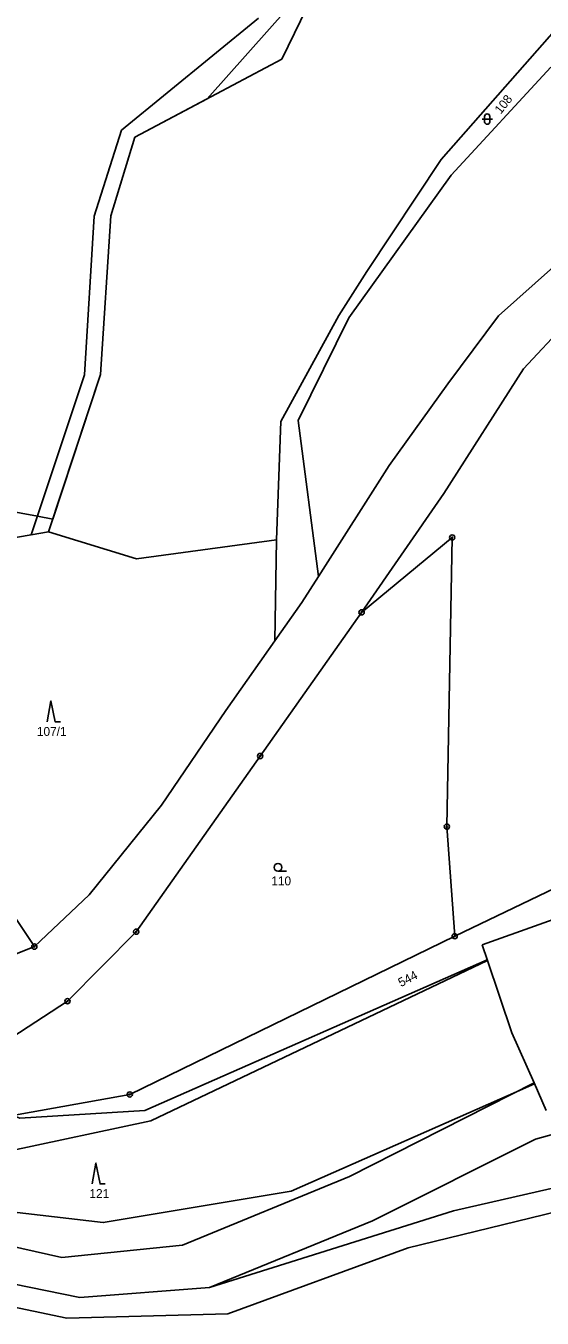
# Model space of a CAD drawing. Extents: x -547623 to -538651, y -1096714 to -1086522.
# Drawn here: x -544480.8 to -544381.9, y -1094558.3 to -1094310.7 of the extents above; entities that cross this region are included whole.
import ezdxf

# ---------------------------------------------------------------- set-up
doc = ezdxf.new("R2010")
doc.units = 0
for name, color, linetype in [('Vrstva 1', 7, 'Continuous'), ('Vrstva 25', 7, 'Continuous'), ('Vrstva 52', 7, 'Continuous'), ('Vrstva 83', 7, 'Continuous'), ('Vrstva 86', 7, 'Continuous')]:
    doc.layers.add(name, color=color, linetype=linetype)

msp = doc.modelspace()

# ---------------------------------------------------------------- linework, layer by layer
at = {"layer": 'Vrstva 1'}
for points in [[(-544419.77, -1094292.39), (-544431.79, -1094317.13)], [(-544401.22, -1094336.37), (-544365.84, -1094296.09)], [(-544462.49, -1094330.71), (-544436.24, -1094309.29)], [(-544431.79, -1094317.13), (-544459.96, -1094332.09)], [(-544380.24, -1094318.64), (-544399.29, -1094339.34)], [(-544467.74, -1094347.2), (-544462.49, -1094330.71)], [(-544459.96, -1094332.09), (-544464.57, -1094347.15)], [(-544415.46, -1094357.78), (-544401.22, -1094336.37)], [(-544399.29, -1094339.34), (-544418.93, -1094366.66)], [(-544469.56, -1094377.62), (-544467.74, -1094347.2)], [(-544464.57, -1094347.15), (-544466.54, -1094377.51)], [(-544420.85, -1094366.26), (-544415.46, -1094357.78)], [(-544390.22, -1094366.32), (-544379.71, -1094356.93)], [(-544431.95, -1094386.55), (-544420.85, -1094366.26)], [(-544418.93, -1094366.66), (-544428.64, -1094386.32)], [(-544399.96, -1094379.3), (-544390.22, -1094366.32)], [(-544385.44, -1094376.43), (-544377.33, -1094367.74)], [(-544469.56, -1094377.62), (-544479.78, -1094408.26)], [(-544476.5, -1094407.7), (-544466.54, -1094377.51)], [(-544400.75, -1094400.36), (-544385.44, -1094376.43)], [(-544411.21, -1094394.96), (-544399.96, -1094379.3)], [(-544432.76, -1094409.19), (-544431.95, -1094386.55)], [(-544428.64, -1094386.32), (-544424.74, -1094416.22)], [(-544424.74, -1094416.22), (-544411.21, -1094394.96)], [(-544416.48, -1094423.1), (-544400.75, -1094400.36)], [(-544479.78, -1094408.26), (-544476.5, -1094407.7)], [(-544476.5, -1094407.7), (-544459.63, -1094412.82)], [(-544485.43, -1094409.22), (-544479.78, -1094408.26)], [(-544459.63, -1094412.82), (-544432.76, -1094409.19)], [(-544432.76, -1094409.19), (-544433.11, -1094428.56)], [(-544416.48, -1094423.1), (-544399.11, -1094408.75)], [(-544399.11, -1094408.75), (-544400.13, -1094464.15)], [(-544427.91, -1094421.19), (-544424.74, -1094416.22)], [(-544433.11, -1094428.56), (-544427.91, -1094421.19)], [(-544435.92, -1094450.63), (-544416.48, -1094423.1)], [(-544442.51, -1094441.89), (-544433.11, -1094428.56)], [(-544454.81, -1094460.05), (-544442.51, -1094441.89)], [(-544459.67, -1094484.27), (-544435.92, -1094450.63)], [(-544479.2, -1094487.13), (-544497.09, -1094460.28)], [(-544468.71, -1094477.24), (-544454.81, -1094460.05)], [(-544400.13, -1094464.15), (-544398.64, -1094485.14)], [(-544393.36, -1094486.79), (-544348.76, -1094470.87)], [(-544398.64, -1094485.14), (-544374.54, -1094473.56)], [(-544479.2, -1094487.13), (-544468.71, -1094477.24)], [(-544472.85, -1094497.6), (-544459.67, -1094484.27)], [(-544494.29, -1094493.18), (-544479.2, -1094487.13)], [(-544398.64, -1094485.14), (-544460.91, -1094515.46)], [(-544393.36, -1094486.79), (-544392.36, -1094489.78)], [(-544456.89, -1094520.54), (-544392.36, -1094489.78)], [(-544392.36, -1094489.78), (-544387.72, -1094503.66)], [(-544483.53, -1094504.55), (-544472.85, -1094497.6)], [(-544387.72, -1094503.66), (-544383.43, -1094513.26)], [(-544418.83, -1094531.18), (-544383.43, -1094513.26)], [(-544383.43, -1094513.26), (-544381.08, -1094518.51)], [(-544460.91, -1094515.46), (-544484.09, -1094519.61)], [(-544383.15, -1094524.05), (-544351.6, -1094515.28)], [(-544484.38, -1094526.41), (-544456.89, -1094520.54)], [(-544383.15, -1094524.05), (-544414.38, -1094539.67)], [(-544418.83, -1094531.18), (-544450.78, -1094544.34)], [(-544362.26, -1094529.36), (-544398.89, -1094537.76)], [(-544407.55, -1094544.87), (-544363.31, -1094534.07)], [(-544473.96, -1094546.71), (-544513.47, -1094537.82)], [(-544398.89, -1094537.76), (-544445.63, -1094552.46)], [(-544414.38, -1094539.67), (-544445.63, -1094552.46)], [(-544470.45, -1094554.36), (-544531.27, -1094541.95)], [(-544450.78, -1094544.34), (-544473.96, -1094546.71)], [(-544442.13, -1094557.51), (-544407.55, -1094544.87)], [(-544510.16, -1094550.54), (-544472.99, -1094558.31)], [(-544445.63, -1094552.46), (-544470.45, -1094554.36)], [(-544472.99, -1094558.31), (-544442.13, -1094557.51)]]:
    msp.add_lwpolyline(points, dxfattribs=at)
at = {"layer": 'Vrstva 25'}
for p, q in [((-544393.4, -1094328.6), (-544391.4, -1094328.6)), ((-544392.9, -1094329.1), (-544392.9, -1094328.1)), ((-544391.9, -1094328.1), (-544391.9, -1094329.1)), ((-544432.5, -1094472.7), (-544430.9, -1094472.7))]:
    msp.add_line(p, q, dxfattribs=at)
for points in [[(-544476.71, -1094444.06), (-544476.01, -1094440.06), (-544475.21, -1094444.06), (-544474.21, -1094444.06)], [(-544468.11, -1094532.59), (-544467.41, -1094528.59), (-544466.61, -1094532.59), (-544465.61, -1094532.59)]]:
    msp.add_lwpolyline(points, dxfattribs=at)
msp.add_circle((-544432.5, -1094471.95), 0.75, dxfattribs=at)
for centre, start, end in [((-544392.4, -1094328.1), 0, 180), ((-544392.4, -1094329.1), 180, 0)]:
    msp.add_arc(centre, 0.5, start, end, dxfattribs=at)
at = {"layer": 'Vrstva 52'}
for points in [[(-544422.69, -1094298.4), (-544446.09, -1094324.72), (-544459.96, -1094332.09), (-544464.57, -1094347.15), (-544466.54, -1094377.51), (-544475.68, -1094405.23), (-544478.59, -1094404.69), (-544490.5, -1094402.5)], [(-544386.24, -1094514.68), (-544430, -1094534), (-544466, -1094540), (-544487.5, -1094537.5), (-544536.5, -1094523.5), (-544567.5, -1094506), (-544566.1, -1094505.65), (-544561.5, -1094504.5), (-544534.5, -1094509), (-544505.75, -1094509.97), (-544505, -1094510), (-544499.48, -1094512.4), (-544499.06, -1094519.67), (-544484.09, -1094519.61), (-544483.24, -1094519.46), (-544482, -1094520), (-544458, -1094518.5), (-544392.4, -1094489.67)], [(-544392.4, -1094489.67), (-544392.36, -1094489.78), (-544387.72, -1094503.66), (-544383.43, -1094513.26), (-544383.36, -1094513.41), (-544386.24, -1094514.68)]]:
    msp.add_lwpolyline(points, dxfattribs=at)
at = {"layer": 'Vrstva 83'}
for centre, radius in [((-544399.11, -1094408.75), 0.5), ((-544399.11, -1094408.75), 0.1), ((-544416.48, -1094423.1), 0.5), ((-544416.48, -1094423.1), 0.1), ((-544435.92, -1094450.63), 0.5), ((-544435.92, -1094450.63), 0.1), ((-544400.13, -1094464.15), 0.5), ((-544400.13, -1094464.15), 0.1), ((-544459.67, -1094484.27), 0.5), ((-544459.67, -1094484.27), 0.1), ((-544398.64, -1094485.14), 0.5), ((-544479.2, -1094487.13), 0.5), ((-544479.2, -1094487.13), 0.1), ((-544398.64, -1094485.14), 0.1), ((-544472.85, -1094497.6), 0.5), ((-544472.85, -1094497.6), 0.1), ((-544460.91, -1094515.46), 0.5), ((-544460.91, -1094515.46), 0.1)]:
    msp.add_circle(centre, radius, dxfattribs=at)

# ---------------------------------------------------------------- texts
at = {"layer": 'Vrstva 86'}
for s, rotation, p in [('108', 51.6964, (-544389.81, -1094327.77)), ('544', 27.5789, (-544408.93, -1094494.91))]:
    msp.add_text(s, height=1.7, rotation=rotation, dxfattribs=at).set_placement(p)
for s, p in [('107/1', (-544478.71, -1094446.76)), ('110', (-544433.79, -1094475.4)), ('121', (-544468.64, -1094535.29))]:
    msp.add_text(s, height=1.7, dxfattribs=at).set_placement(p)

doc.saveas('drawing.dxf')
